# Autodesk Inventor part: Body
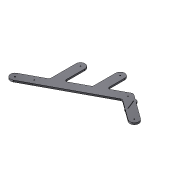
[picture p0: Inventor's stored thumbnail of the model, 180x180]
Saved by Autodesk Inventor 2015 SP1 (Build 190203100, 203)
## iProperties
Created: 2015-01
Part Number: Body
Material: Generic
Document SubType Name: Modeling
Designer: Steve Brooks
Density: 1 g/cm^3
Appearance: Machined 02
Author: Steve Brooks
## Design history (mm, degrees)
sketch "Sketch1"
  geometry: L1 (508.303, 76.266)-(508.303, 76.255); L2 (343.915, 195.691)-(343.915, 195.681); L3 (-93.042, -38.761)-(-93.042, -38.771); L4 (-182.856, -86.94)-(-182.856, -86.95); L5 (347.829, 153.603)-(397.575, 117.459); L6 (335.976, 227.464)-(237.968, 174.868); L7 (-51.599, 19.512)-(-108.073, -10.795); L8 (-108.073, -10.795)-(-197.868, -58.973); L9 (-167.837, -114.929)-(-78.035, -66.762); L10 (-78.035, -66.762)-(334.349, 154.52); L11 (-44.904, 212.354)-(-44.909, 30.698); L12 (383.391, 206.253)-(356.051, 226.107); L13 (18.591, 78.394)-(18.591, 212.354); L14 (149.051, 127.167)-(37.3, 67.206); L15 (155.741, 295.953)-(155.751, 138.353); L16 (219.241, 186.061)-(219.241, 295.955); L17 (526.967, 101.945)-(415.693, 182.771); L18 (420.631, 100.709)-(489.655, 50.563); C1 r 3.175 at (-13.159, 212.354); C2 r 3.175 at (187.491, 295.955); C3 r 3.175 at (343.915, 195.686); C4 r 3.175 at (508.303, 76.261); C5 r 3.175 at (-93.042, -38.766); C6 r 4.762 at (-182.856, -86.945); A1 r 650.611 centre (-197.536, -93.117) between (416.813, 121.056) and (391.036, 184.151); A2 r 661.04 centre (-204.299, -95.677) between (420.009, 121.609) and (393.951, 185.52); A3 r 1.622 centre (418.411, 121.333) between (416.813, 121.056) and (420.009, 121.609); A4 r 1.61 centre (392.499, 184.823) between (393.951, 185.52) and (391.036, 184.151); A5 r 12.702 centre (340.359, 143.33) between (347.829, 153.603) and (334.349, 154.52); A6 r 12.558 centre (390.231, 107.273) between (401.394, 113.024) and (397.575, 117.459); A7 r 12.705 centre (231.946, 186.055) between (219.241, 186.061) and (237.968, 174.868); A8 r 31.752 centre (-182.846, -86.948) between (-197.868, -58.973) and (-167.837, -114.929); A9 r 31.747 centre (-13.156, 212.356) between (18.591, 212.354) and (-44.904, 212.354); A10 r 12.7 centre (31.291, 78.394) between (18.591, 78.394) and (37.3, 67.206); A11 r 12.677 centre (143.074, 138.347) between (149.051, 127.167) and (155.751, 138.353); A12 r 12.668 centre (-57.576, 30.681) between (-51.599, 19.512) and (-44.909, 30.698); A13 r 31.75 centre (187.491, 295.954) between (219.241, 295.955) and (155.741, 295.953); A14 r 12.643 centre (390.842, 216.467) between (383.391, 206.253) and (391.504, 203.841); A15 r 18.986 centre (344.928, 210.721) between (356.051, 226.107) and (335.976, 227.464); A16 r 19.031 centre (392.501, 184.837) between (410.88, 189.775) and (391.504, 203.841); A17 r 12.714 centre (423.163, 193.06) between (410.88, 189.775) and (415.693, 182.771); A18 r 31.75 centre (508.311, 76.254) between (489.655, 50.563) and (526.967, 101.945); A19 r 31.75 centre (508.311, 76.254) between (489.655, 50.563) and (489.655, 50.563); A20 r 31.75 centre (508.311, 76.254) between (489.655, 50.563) and (489.655, 50.563); A21 r 12.697 centre (413.161, 90.441) between (420.631, 100.709) and (415.216, 102.971); A22 r 19.037 centre (418.311, 121.755) between (401.394, 113.024) and (415.216, 102.971); 1 further point
  constraints: 44 point on circle, 36 end point, 28 centre point
extrude "Extrusion1" new body sketch "Sketch1" distance "d0" = 12; taper "d1" = 0 deg
body "Solid1"
